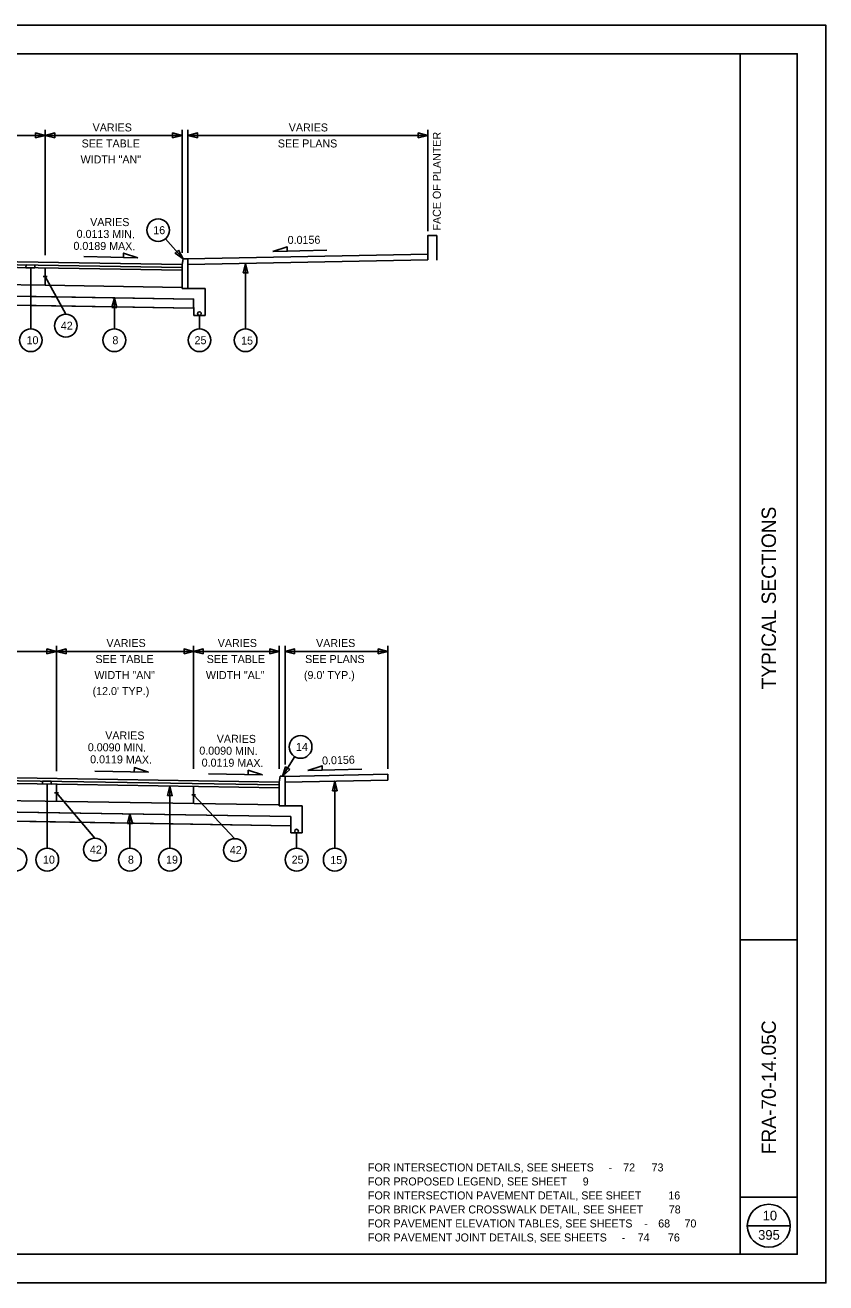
# Model space of a CAD drawing. Extents: x -529 to 1, y -1131 to -115.
# Drawn here: x -329.4 to -189.3, y -1130.8 to -910.8 of the extents above; entities that cross this region are included whole.
import ezdxf

# ---------------------------------------------------------------- set-up
doc = ezdxf.new("R2010")
doc.units = 0
for name, color, linetype in [('GE_X_CL_10', 7, 'Continuous'), ('PV_P_EOP', 7, 'Continuous'), ('PV_X_EOP', 7, 'Continuous'), ('SH_Border', 7, 'Continuous'), ('SH_Cut_Line', 7, 'Continuous'), ('SH_Data', 7, 'Continuous'), ('SH_Text', 7, 'Continuous'), ('XS_X_Ground_Line', 7, 'Continuous')]:
    doc.layers.add(name, color=color, linetype=linetype)

msp = doc.modelspace()

# ---------------------------------------------------------------- linework, layer by layer
at = {"layer": 'PV_P_EOP'}
for p, q in [((-356.79, -951.75), (-301.95, -952.63)), ((-356.79, -952.25), (-301.95, -953.13)), ((-301.95, -952.63), (-301.79, -951.63)), ((-301.79, -951.63), (-300.95, -951.63)), ((-300.95, -951.63), (-258.95, -950.79)), ((-300.95, -956.81), (-300.95, -951.63)), ((-300.95, -952.63), (-258.95, -951.79)), ((-258.95, -951.79), (-258.95, -950.79)), ((-356.79, -952.75), (-301.95, -953.63)), ((-325.95, -956.24), (-325.95, -953.24)), ((-301.95, -952.84), (-301.95, -952.63)), ((-301.95, -956.81), (-301.95, -952.63)), ((-301.95, -953.13), (-301.95, -952.84)), ((-301.95, -953.79), (-301.95, -953.13)), ((-301.95, -954.63), (-301.95, -953.79)), ((-356.79, -955.75), (-325.95, -956.24)), ((-325.95, -956.24), (-301.94, -956.63)), ((-300.95, -956.81), (-301.95, -956.81)), ((-297.94, -956.81), (-301.95, -956.81)), ((-297.94, -959.05), (-297.94, -956.81)), ((-356.79, -957.75), (-299.95, -958.66)), ((-356.79, -959.35), (-299.95, -960.26)), ((-356.79, -1042.01), (-284.95, -1043.15)), ((-356.79, -1042.51), (-284.95, -1043.65)), ((-284.95, -1043.15), (-284.79, -1042.15)), ((-284.79, -1042.15), (-283.95, -1042.15)), ((-283.95, -1042.16), (-265.95, -1041.8)), ((-283.95, -1047.33), (-283.95, -1042.15)), ((-265.95, -1042.8), (-265.95, -1041.8)), ((-356.79, -1043.01), (-284.95, -1044.15)), ((-323.95, -1046.53), (-323.95, -1043.53)), ((-299.95, -1046.91), (-299.95, -1043.91)), ((-284.95, -1043.36), (-284.95, -1043.15)), ((-284.95, -1047.33), (-284.95, -1043.15)), ((-284.95, -1043.65), (-284.95, -1043.36)), ((-284.95, -1044.32), (-284.95, -1043.65)), ((-284.95, -1045.15), (-284.95, -1044.32)), ((-283.95, -1043.16), (-265.95, -1042.8)), ((-356.79, -1046.01), (-325.95, -1046.5)), ((-325.95, -1046.5), (-284.95, -1047.15)), ((-356.79, -1048.01), (-282.95, -1049.19)), ((-283.95, -1047.33), (-284.95, -1047.33)), ((-280.94, -1047.33), (-284.95, -1047.33)), ((-280.94, -1049.58), (-280.94, -1047.33)), ((-356.79, -1049.61), (-282.95, -1050.79))]:
    msp.add_line(p, q, dxfattribs=at)
at = {"layer": 'PV_X_EOP'}
for p, q in [((-326.28, -954.74), (-325.6, -954.74)), ((-322.32, -961.34), (-325.95, -954.74)), ((-299.95, -958.66), (-299.94, -961.52)), ((-297.94, -959.05), (-297.94, -961.52)), ((-299.94, -961.52), (-297.94, -961.52)), ((-324.28, -1045.03), (-323.6, -1045.03)), ((-317.23, -1052.98), (-323.95, -1045.03)), ((-300.28, -1045.41), (-299.6, -1045.41)), ((-292.74, -1053.06), (-299.95, -1045.41)), ((-282.95, -1049.19), (-282.94, -1052.05)), ((-280.94, -1049.58), (-280.94, -1052.05)), ((-282.94, -1052.05), (-280.94, -1052.05))]:
    msp.add_line(p, q, dxfattribs=at)
at = {"layer": 'SH_Border'}
for p, q in [((-204.28, -1125.76), (-204.28, -915.76)), ((-204.28, -1070.76), (-194.28, -1070.76)), ((-204.28, -1115.76), (-194.28, -1115.76))]:
    msp.add_line(p, q, dxfattribs=at)
msp.add_lwpolyline([(-509.28, -915.76), (-194.28, -915.76), (-194.28, -1125.76), (-509.28, -1125.76)], close=True, dxfattribs=at)
at = {"layer": 'SH_Cut_Line'}
msp.add_lwpolyline([(-529.28, -1130.76), (-189.28, -1130.76), (-189.28, -910.76), (-529.28, -910.76)], close=True, dxfattribs=at)
at = {"layer": 'SH_Data'}
for p, q in [((-325.95, -929.08), (-325.95, -951.02)), ((-301.95, -929.08), (-301.95, -950.58)), ((-300.95, -929.08), (-300.95, -950.58)), ((-258.95, -929.08), (-258.95, -946.79)), ((-323.95, -1019.33), (-323.95, -1041.28)), ((-299.95, -1019.33), (-299.95, -1040.83)), ((-284.95, -1019.33), (-284.95, -1040.83)), ((-283.95, -1019.33), (-283.95, -1040.11)), ((-265.95, -1019.33), (-265.95, -1040.83)), ((-203.03, -1120.76), (-195.53, -1120.76))]:
    msp.add_line(p, q, dxfattribs=at)
for points in [[(-299.95, -960.26), (-356.79, -959.35), (-412.55, -960.24), (-412.55, -958.64), (-356.79, -957.75), (-299.95, -958.66)], [(-430.95, -1050.79), (-356.79, -1049.61), (-282.95, -1050.79), (-282.95, -1049.19), (-356.79, -1048.01), (-430.95, -1049.19)]]:
    msp.add_lwpolyline(points, close=True, dxfattribs=at)
msp.add_circle((-199.28, -1120.76), 3.75, dxfattribs=at)
at = {"layer": 'SH_Text'}
for p, q in [((-301.95, -930.04), (-356.95, -930.04)), ((-258.95, -930.04), (-300.95, -930.04)), ((-301.79, -951.63), (-304.85, -948.12)), ((-286.06, -950.36), (-276.63, -950.14)), ((-309.72, -951.45), (-319.15, -951.23)), ((-290.86, -963.88), (-290.86, -952.43)), ((-328.45, -963.88), (-328.45, -953.16)), ((-313.83, -963.88), (-313.83, -958.44)), ((-298.92, -963.88), (-298.92, -961.51)), ((-284.95, -1020.3), (-356.95, -1020.3)), ((-265.95, -1020.3), (-283.95, -1020.3)), ((-282.26, -1038.71), (-284.37, -1042.15)), ((-307.84, -1041.45), (-317.27, -1041.23)), ((-287.91, -1041.92), (-297.34, -1041.7)), ((-279.96, -1041.13), (-270.53, -1040.91)), ((-325.57, -1054.74), (-325.57, -1043.5)), ((-304.11, -1054.74), (-304.11, -1043.85)), ((-275.25, -1054.74), (-275.25, -1042.99)), ((-311.1, -1054.74), (-311.1, -1048.74)), ((-281.92, -1054.74), (-281.92, -1052.04))]:
    msp.add_line(p, q, dxfattribs=at)
for points in [[(-327.63, -930.46), (-325.95, -930.04), (-327.63, -929.62)], [(-324.27, -930.46), (-325.95, -930.04), (-324.27, -929.62)], [(-303.63, -930.46), (-301.95, -930.04), (-303.63, -929.62)], [(-299.27, -930.46), (-300.95, -930.04), (-299.27, -929.62)], [(-260.63, -930.46), (-258.95, -930.04), (-260.63, -929.62)], [(-302.58, -950.09), (-301.79, -951.63), (-303.21, -950.64)], [(-286.06, -950.36), (-283.56, -950.3), (-283.56, -949.54)], [(-309.72, -951.45), (-312.22, -951.39), (-312.21, -950.63)], [(-291.28, -954.11), (-290.86, -952.43), (-290.44, -954.11)], [(-329.28, -952.69), (-329.31, -953.19), (-327.77, -953.22), (-327.76, -952.72)], [(-314.25, -960.12), (-313.83, -958.44), (-313.41, -960.12)], [(-325.63, -1020.72), (-323.95, -1020.3), (-325.63, -1019.88)], [(-322.27, -1020.72), (-323.95, -1020.3), (-322.27, -1019.88)], [(-301.63, -1020.72), (-299.95, -1020.3), (-301.63, -1019.88)], [(-298.27, -1020.72), (-299.95, -1020.3), (-298.27, -1019.88)], [(-286.63, -1020.72), (-284.95, -1020.3), (-286.63, -1019.88)], [(-282.27, -1020.72), (-283.95, -1020.3), (-282.27, -1019.88)], [(-267.63, -1020.72), (-265.95, -1020.3), (-267.63, -1019.88)], [(-283.14, -1040.94), (-284.37, -1042.15), (-283.85, -1040.5)], [(-279.96, -1041.13), (-277.46, -1041.08), (-277.47, -1040.31)], [(-307.84, -1041.45), (-310.34, -1041.39), (-310.33, -1040.63)], [(-287.91, -1041.92), (-290.41, -1041.86), (-290.4, -1041.1)], [(-326.39, -1042.99), (-326.42, -1043.49), (-324.89, -1043.52), (-324.88, -1043.02)], [(-304.53, -1045.53), (-304.11, -1043.85), (-303.69, -1045.53)], [(-275.67, -1044.67), (-275.25, -1042.99), (-274.83, -1044.67)], [(-311.52, -1050.42), (-311.1, -1048.74), (-310.68, -1050.42)]]:
    msp.add_lwpolyline(points, close=True, dxfattribs=at)
for centre, radius in [((-306.16, -946.62), 1.99), ((-322.32, -963.33), 1.99), ((-298.94, -961.2), 0.319), ((-328.45, -965.87), 1.99), ((-313.83, -965.87), 1.99), ((-298.92, -965.87), 1.99), ((-290.86, -965.87), 1.99), ((-281.23, -1037.01), 1.99), ((-281.94, -1051.73), 0.319), ((-317.23, -1054.97), 1.99), ((-292.74, -1055.05), 1.99), ((-331.16, -1056.73), 1.99), ((-325.57, -1056.73), 1.99), ((-311.1, -1056.73), 1.99), ((-304.11, -1056.73), 1.99), ((-281.92, -1056.73), 1.99), ((-275.25, -1056.73), 1.99)]:
    msp.add_circle(centre, radius, dxfattribs=at)
at = {"layer": 'XS_X_Ground_Line'}
msp.add_lwpolyline([(-257.39, -951.85), (-257.39, -947.56), (-258.97, -947.57), (-258.97, -949.35), (-258.95, -951.79)], dxfattribs=at)

# ---------------------------------------------------------------- texts
at = {"layer": 'GE_X_CL_10'}
msp.add_text('FACE OF PLANTER', height=1.4, rotation=90, dxfattribs=at).set_placement((-256.68, -946.69))
at = {"layer": 'SH_Data'}
for s, p in [('       TYPICAL SECTIONS       ', (-198.03, -1033.44)), ('FRA-70-14.05C', (-198.03, -1108.26))]:
    msp.add_text(s, height=2.5, rotation=90, dxfattribs=at).set_placement(p)
for s, height, p in [('72', 1.4, (-224.76, -1111.27)), ('73', 1.4, (-219.79, -1111.27)), ('9', 1.4, (-231.84, -1113.72)), ('16', 1.4, (-216.86, -1116.17)), ('78', 1.4, (-216.78, -1118.62)), ('68', 1.4, (-218.63, -1121.07)), ('70', 1.4, (-214.03, -1121.07)), ('10', 1.7, (-200.35, -1119.84)), ('395', 1.7, (-201.14, -1123.22)), ('74', 1.4, (-222.23, -1123.52)), ('76', 1.4, (-216.93, -1123.52))]:
    msp.add_text(s, height=height, dxfattribs=at).set_placement(p)
at = {"layer": 'SH_Text'}
for s, p in [('VARIES', (-317.63, -929.35)), ('VARIES', (-283.3, -929.35)), ('SEE TABLE', (-319.56, -932.15)), ('SEE PLANS', (-285.21, -932.15)), ('WIDTH "AN"', (-319.74, -934.95)), ('16', (-307.02, -947.32)), ('42', (-323.2, -964.03)), ('10', (-329.2, -966.57)), ('8', (-314.17, -966.57)), ('25', (-299.79, -966.57)), ('15', (-291.64, -966.63)), ('VARIES', (-315.21, -1019.54)), ('VARIES', (-295.73, -1019.54)), ('VARIES', (-278.52, -1019.54)), ('SEE TABLE', (-317.14, -1022.34)), ('SEE TABLE', (-297.66, -1022.34)), ('SEE PLANS', (-280.43, -1022.34)), ('WIDTH "AN"', (-317.32, -1025.14)), ('WIDTH "AL"', (-297.81, -1025.14)), ("(9.0' TYP.)", (-280.64, -1025.14)), ("(12.0' TYP.)", (-317.64, -1027.94)), ('14', (-282.04, -1037.71)), ('42', (-318.11, -1055.67)), ('42', (-293.62, -1055.75)), ('10', (-326.32, -1057.43)), ('8', (-311.45, -1057.43)), ('19', (-304.78, -1057.43)), ('25', (-282.79, -1057.43)), ('15', (-276.02, -1057.5)), ('FOR INTERSECTION DETAILS, SEE SHEETS     -  ', (-269.44, -1111.27)), ('FOR PROPOSED LEGEND, SEE SHEET', (-269.44, -1113.72)), ('FOR INTERSECTION PAVEMENT DETAIL, SEE SHEET', (-269.44, -1116.17)), ('FOR BRICK PAVER CROSSWALK DETAIL, SEE SHEET ', (-269.44, -1118.62)), ('FOR PAVEMENT ELEVATION TABLES, SEE SHEETS    -', (-269.44, -1121.07)), ('FOR PAVEMENT JOINT DETAILS, SEE SHEETS     - ', (-269.44, -1123.52))]:
    msp.add_text(s, height=1.4, dxfattribs=at).set_placement(p)
for s, rotation, p in [('VARIES', 359.6389, (-318.07, -945.87)), ('0.0113 MIN.', 359.6389, (-320.44, -947.96)), ('0.0156', 0.3611, (-283.49, -949.03)), ('0.0189 MAX.', 359.6389, (-320.99, -950.06)), ('VARIES', 359.6389, (-315.43, -1035.68)), ('VARIES', 359.6389, (-295.91, -1036.27)), ('0.0090 MIN.', 359.6389, (-318.48, -1037.76)), ('0.0090 MIN.', 359.6389, (-298.96, -1038.35)), ('0.0119 MAX.', 359.6389, (-318.07, -1039.87)), ('0.0119 MAX.', 359.6389, (-298.55, -1040.45)), ('0.0156', 1.6982, (-277.45, -1040.1))]:
    msp.add_text(s, height=1.4, rotation=rotation, dxfattribs=at).set_placement(p)

doc.saveas('drawing.dxf')
